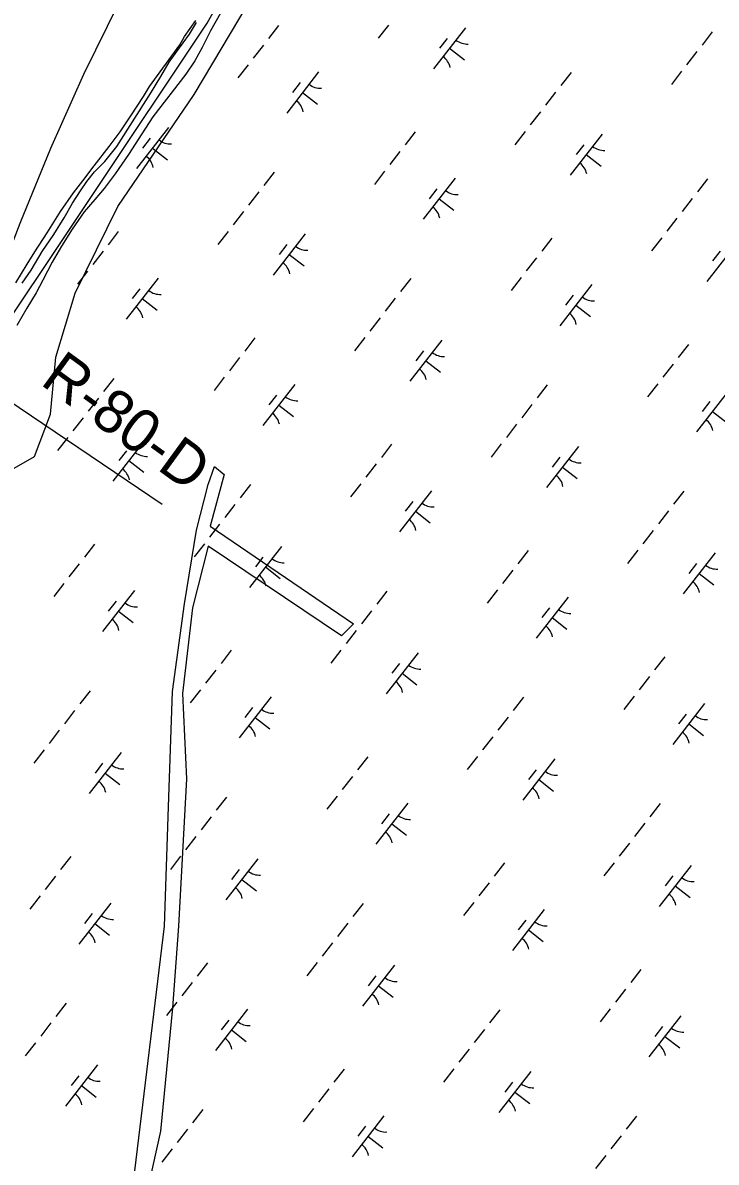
# Model space of a CAD drawing. Extents: x 3888273 to 3909528, y 158682 to 181032.
# Drawn here: x 3898444 to 3899111, y 163473 to 164568 of the extents above; entities that cross this region are included whole.
import ezdxf

# ---------------------------------------------------------------- set-up
doc = ezdxf.new("R2010")
doc.units = 0
for name, color, linetype in [('V-GRID-MAJR', 7, 'Continuous'), ('V-LEVE-TOET', 7, 'Continuous'), ('V-RIVR-EDGE', 7, 'Continuous'), ('V-RIVR-JETY', 7, 'Continuous'), ('V-RIVR-RANG-IDEN', 7, 'Continuous'), ('V-RRAP-FSHR', 7, 'Continuous'), ('V-TOPO-DPTH', 7, 'Continuous'), ('V-TOPO-MINR', 7, 'Continuous'), ('V-WETL-SWMP', 7, 'Continuous')]:
    doc.layers.add(name, color=color, linetype=linetype)

msp = doc.modelspace()

# ---------------------------------------------------------------- linework, layer by layer
at = {"layer": 'V-GRID-MAJR'}
msp.add_spline([(3899339.3, 161091.9), (3899310.2, 162813.4), (3899208, 168873.7), (3899105.7, 174933.9), (3899088.2, 175974.6)], degree=3, dxfattribs=at)
at = {"layer": 'V-LEVE-TOET'}
msp.add_lwpolyline([(3898578.1, 164105.2), (3898383.3, 164236.8), (3898266.7, 164315.1), (3898154.4, 164391.2), (3898098.5, 164425.2)], dxfattribs=at)
at = {"layer": 'V-RIVR-EDGE'}
msp.add_lwpolyline([(3898431.6, 164137.7), (3898455.5, 164151.3), (3898470.9, 164192.2), (3898476, 164246.8), (3898494.7, 164308.2), (3898535.6, 164391.7), (3898609, 164499.1), (3898661.8, 164587.8)], dxfattribs=at)
at = {"layer": 'V-RIVR-JETY'}
for points in [[(3898634.3, 164577.4), (3898624.8, 164560.4), (3898616.6, 164544.4), (3898609.6, 164531.7), (3898601, 164518.9), (3898569.4, 164477.7), (3898558.6, 164461.3), (3898545.9, 164441.7), (3898533.1, 164423.1), (3898522.6, 164409), (3898513.6, 164398.5), (3898503.4, 164386.4), (3898491.9, 164370), (3898481.5, 164353.4), (3898472.6, 164338), (3898463.7, 164321), (3898457, 164308.6), (3898448.1, 164293.9), (3898438.6, 164277.3)], [(3898443.6, 164317.9), (3898452.2, 164330.3), (3898463, 164348.3), (3898474.2, 164364.6), (3898484, 164380.6), (3898492, 164394.7), (3898499.9, 164406.8), (3898506, 164415.6), (3898513.3, 164424.8), (3898523.2, 164434.9), (3898534.7, 164449.4), (3898566.9, 164500.3), (3898577, 164516.4), (3898585, 164530.4), (3898592.3, 164540.6), (3898604.4, 164557.2), (3898611.4, 164568.4)], [(3898551.9, 163465.1), (3898580.6, 163700.2), (3898584.4, 163814.9), (3898588.2, 163925.7), (3898599.7, 164009.8), (3898611.2, 164080.5), (3898622.6, 164124.5), (3898628.4, 164141.7), (3898637.9, 164134.1), (3898624.5, 164084.4), (3898762.2, 163990.7), (3898750.7, 163979.2), (3898622.6, 164065.2), (3898607.3, 164006), (3898597.8, 163923.8), (3898601.6, 163841.6), (3898597.8, 163770.9), (3898594, 163700.2), (3898588.2, 163621.8), (3898576.8, 163503.3), (3898551.9, 163392.5)]]:
    msp.add_lwpolyline(points, dxfattribs=at)
at = {"layer": 'V-RRAP-FSHR'}
msp.add_lwpolyline([(3897334.5, 161278.4), (3897347.1, 161496.1), (3897391.7, 162468.6), (3897415, 162511), (3897527.9, 162698.5), (3897668.8, 162942.7), (3897726.7, 163035.8), (3897814.8, 163180.2), (3897887.5, 163323.2), (3898044.9, 163635.1), (3898398.2, 164233.6), (3898621.6, 164567.9), (3898731.9, 164766.1)], dxfattribs=at)
at = {"layer": 'V-TOPO-DPTH'}
msp.add_lwpolyline([(3897709.5, 163168.8), (3897726, 163254.6), (3897958.8, 163561.8), (3898413.5, 164303), (3898441.8, 164375.6), (3898471.1, 164447.7), (3898502.9, 164518.7), (3898537.2, 164588.3), (3898575.2, 164656), (3898615.6, 164722.5), (3898745.8, 164924.5), (3898762, 164947.9), (3898778.9, 164970.6), (3898797.2, 164992.4), (3898816.4, 165013.4), (3898843.6, 165041.6)], dxfattribs=at)
at = {"layer": 'V-TOPO-MINR'}
msp.add_lwpolyline([(3897709.5, 163168.8), (3897726, 163254.6), (3897958.8, 163561.8), (3898413.5, 164303), (3898441.8, 164375.6), (3898471.1, 164447.7), (3898502.9, 164518.7), (3898537.2, 164588.3), (3898575.2, 164656), (3898615.6, 164722.5), (3898745.8, 164924.5), (3898762, 164947.9), (3898778.9, 164970.6), (3898797.2, 164992.4), (3898816.4, 165013.4), (3898843.6, 165041.6)], dxfattribs=at)
at = {"layer": 'V-WETL-SWMP'}
for p, q in [((3898599.6, 164555), (3898610.5, 164570.4)), ((3898690.2, 164565.6), (3898680.4, 164552.9)), ((3898795.7, 164565.8), (3898785.9, 164553.2)), ((3898869.8, 164563.3), (3898839.1, 164523.9)), ((3898595.1, 164546.8), (3898599.6, 164555)), ((3898852.1, 164553.1), (3898844.7, 164543.6)), ((3899106.9, 164559.3), (3899097.1, 164546.7)), ((3898566, 164506.9), (3898595.1, 164546.8)), ((3898675.5, 164546.6), (3898665.7, 164534)), ((3898854.5, 164543.6), (3898868.7, 164532.6)), ((3899092.2, 164540.4), (3899082.3, 164527.8)), ((3898660.8, 164527.7), (3898650.9, 164515.1)), ((3898728.6, 164520.9), (3898697.9, 164481.4)), ((3898971.2, 164520.5), (3898961.4, 164507.9)), ((3899077.4, 164521.5), (3899067.6, 164508.8)), ((3898560.4, 164497.3), (3898566, 164506.9)), ((3898710.8, 164510.6), (3898703.5, 164501.2)), ((3898548, 164478.7), (3898560.4, 164497.3)), ((3898713.2, 164501.2), (3898727.4, 164490.1)), ((3898956.4, 164501.5), (3898946.6, 164488.9)), ((3898537.8, 164463.2), (3898548, 164478.7)), ((3898941.7, 164482.6), (3898931.9, 164470)), ((3898527.2, 164449.3), (3898537.8, 164463.2)), ((3898584.4, 164467.4), (3898553.7, 164428)), ((3898821.5, 164463.4), (3898811.7, 164450.8)), ((3898927, 164463.7), (3898917.1, 164451)), ((3898566.7, 164457.2), (3898559.3, 164447.7)), ((3899001.1, 164461.2), (3898970.4, 164421.7)), ((3898512.9, 164430.7), (3898527.2, 164449.3)), ((3898569.1, 164447.7), (3898583.3, 164436.6)), ((3898806.8, 164444.5), (3898796.9, 164431.9)), ((3898983.4, 164450.9), (3898976, 164441.5)), ((3898985.8, 164441.5), (3899000, 164430.4)), ((3898501.9, 164416.3), (3898512.9, 164430.7)), ((3898685.8, 164424.6), (3898676, 164411.9)), ((3898792, 164425.5), (3898782.2, 164412.9)), ((3898859.9, 164418.7), (3898829.2, 164379.3)), ((3898492.9, 164404.7), (3898501.9, 164416.3)), ((3898842.1, 164408.5), (3898834.7, 164399)), ((3899102.5, 164418.3), (3899092.6, 164405.7)), ((3898480.4, 164386.9), (3898492.9, 164404.7)), ((3898671.1, 164405.6), (3898661.2, 164393)), ((3898844.5, 164399), (3898858.7, 164388)), ((3899087.7, 164399.4), (3899077.9, 164386.8)), ((3898467.6, 164366.4), (3898480.4, 164386.9)), ((3898656.3, 164386.7), (3898646.5, 164374.1)), ((3899073, 164380.5), (3899063.2, 164367.8)), ((3898455.9, 164348.2), (3898467.6, 164366.4)), ((3898536.1, 164367.5), (3898526.3, 164354.9)), ((3898641.6, 164367.7), (3898631.8, 164355.1)), ((3898715.7, 164365.3), (3898685, 164325.8)), ((3898698, 164355), (3898690.6, 164345.5)), ((3898952.8, 164361.3), (3898943, 164348.7)), ((3899058.3, 164361.5), (3899048.4, 164348.9)), ((3899132.4, 164359), (3899101.7, 164319.6)), ((3898448.4, 164336.2), (3898455.9, 164348.2)), ((3898521.4, 164348.6), (3898511.6, 164335.9)), ((3898700.4, 164345.5), (3898714.6, 164334.5)), ((3898938.1, 164342.3), (3898928.2, 164329.7)), ((3899114.6, 164348.8), (3899107.3, 164339.3)), ((3898437.5, 164318.4), (3898448.4, 164336.2)), ((3898506.6, 164329.6), (3898496.8, 164317)), ((3898574.5, 164322.8), (3898543.8, 164283.4)), ((3898817.1, 164322.4), (3898807.3, 164309.8)), ((3898923.3, 164323.4), (3898913.5, 164310.8)), ((3898556.7, 164312.6), (3898549.4, 164303.1)), ((3898991.2, 164316.6), (3898960.4, 164277.1)), ((3898559.1, 164303.1), (3898573.3, 164292)), ((3898802.3, 164303.5), (3898792.5, 164290.9)), ((3898973.4, 164306.3), (3898966, 164296.9)), ((3898975.8, 164296.9), (3898990, 164285.8)), ((3898787.6, 164284.5), (3898777.8, 164271.9)), ((3898667.4, 164265.4), (3898657.6, 164252.7)), ((3898772.9, 164265.6), (3898763, 164253)), ((3898847, 164263.1), (3898816.3, 164223.7)), ((3899084.1, 164259.1), (3899074.2, 164246.5)), ((3898652.7, 164246.4), (3898642.8, 164233.8)), ((3898829.3, 164252.9), (3898821.9, 164243.4)), ((3898831.7, 164243.4), (3898845.9, 164232.3)), ((3899069.3, 164240.2), (3899059.5, 164227.6)), ((3898531.7, 164226.5), (3898521.9, 164213.9)), ((3898637.9, 164227.5), (3898628.1, 164214.8)), ((3898705.8, 164220.7), (3898675.1, 164181.2)), ((3898688, 164210.4), (3898680.6, 164201)), ((3898948.4, 164220.3), (3898938.5, 164207.7)), ((3899054.6, 164221.3), (3899044.8, 164208.6)), ((3899122.4, 164214.5), (3899091.7, 164175)), ((3898517, 164207.6), (3898507.1, 164194.9)), ((3898690.4, 164200.9), (3898704.6, 164189.9)), ((3898933.6, 164201.3), (3898923.8, 164188.7)), ((3899104.7, 164204.2), (3899097.3, 164194.7)), ((3898502.2, 164188.6), (3898492.4, 164176)), ((3899107.1, 164194.7), (3899121.3, 164183.7)), ((3898918.9, 164182.4), (3898909.1, 164169.8)), ((3898487.5, 164169.7), (3898477.7, 164157.1)), ((3898561.6, 164167.2), (3898530.9, 164127.7)), ((3898543.9, 164157), (3898536.5, 164147.5)), ((3898798.7, 164163.2), (3898788.9, 164150.6)), ((3898904.1, 164163.5), (3898894.3, 164150.8)), ((3898978.3, 164161), (3898947.6, 164121.5)), ((3898546.3, 164147.5), (3898560.5, 164136.4)), ((3898960.5, 164150.7), (3898953.2, 164141.3)), ((3898783.9, 164144.3), (3898774.1, 164131.6)), ((3898962.9, 164141.3), (3898977.1, 164130.2)), ((3898663, 164124.4), (3898653.1, 164111.7)), ((3898769.2, 164125.3), (3898759.4, 164112.7)), ((3898837, 164118.5), (3898806.3, 164079.1)), ((3899079.6, 164118.1), (3899069.8, 164105.5)), ((3898648.2, 164105.4), (3898638.4, 164092.8)), ((3898819.3, 164108.3), (3898811.9, 164098.8)), ((3898821.7, 164098.8), (3898835.9, 164087.8)), ((3899064.9, 164099.2), (3899055.1, 164086.6)), ((3898633.5, 164086.5), (3898623.7, 164073.9)), ((3899050.2, 164080.3), (3899040.3, 164067.6)), ((3898513.3, 164067.3), (3898503.5, 164054.7)), ((3898618.8, 164067.5), (3898608.9, 164054.9)), ((3898692.9, 164065.1), (3898662.2, 164025.6)), ((3898930, 164061.1), (3898920.1, 164048.4)), ((3899035.4, 164061.3), (3899025.6, 164048.7)), ((3899109.6, 164058.8), (3899078.9, 164019.4)), ((3898498.6, 164048.4), (3898488.7, 164035.7)), ((3898675.1, 164054.8), (3898667.8, 164045.3)), ((3899091.8, 164048.6), (3899084.4, 164039.1)), ((3898677.6, 164045.3), (3898691.8, 164034.3)), ((3898915.2, 164042.1), (3898905.4, 164029.5)), ((3899094.2, 164039.1), (3899108.4, 164028.1)), ((3898483.8, 164029.4), (3898474, 164016.8)), ((3898551.7, 164022.6), (3898521, 163983.2)), ((3898794.3, 164022.2), (3898784.4, 164009.6)), ((3898900.5, 164023.2), (3898890.7, 164010.6)), ((3898968.3, 164016.4), (3898937.6, 163976.9)), ((3898533.9, 164012.4), (3898526.5, 164002.9)), ((3898536.3, 164002.9), (3898550.5, 163991.8)), ((3898779.5, 164003.3), (3898769.7, 163990.6)), ((3898950.6, 164006.1), (3898943.2, 163996.7)), ((3898953, 163996.7), (3898967.2, 163985.6)), ((3898764.8, 163984.3), (3898755, 163971.7)), ((3898644.6, 163965.2), (3898634.8, 163952.5)), ((3898750, 163965.4), (3898740.2, 163952.8)), ((3898824.2, 163962.9), (3898793.5, 163923.5)), ((3899061.2, 163958.9), (3899051.4, 163946.3)), ((3898806.4, 163952.7), (3898799.1, 163943.2)), ((3898629.8, 163946.2), (3898620, 163933.6)), ((3898808.8, 163943.2), (3898823, 163932.1)), ((3899046.5, 163940), (3899036.7, 163927.4)), ((3898508.9, 163926.3), (3898499, 163913.7)), ((3898615.1, 163927.3), (3898605.3, 163914.6)), ((3898682.9, 163920.5), (3898652.2, 163881)), ((3898925.5, 163920.1), (3898915.7, 163907.4)), ((3899031.8, 163921), (3899021.9, 163908.4)), ((3898494.1, 163907.4), (3898484.3, 163894.7)), ((3898665.2, 163910.2), (3898657.8, 163900.7)), ((3899099.6, 163914.2), (3899068.9, 163874.8)), ((3899081.9, 163904), (3899074.5, 163894.5)), ((3898667.6, 163900.7), (3898681.8, 163889.7)), ((3898910.8, 163901.1), (3898901, 163888.5)), ((3899084.3, 163894.5), (3899098.5, 163883.5)), ((3898479.4, 163888.4), (3898469.6, 163875.8)), ((3898896.1, 163882.2), (3898886.2, 163869.6)), ((3898464.7, 163869.5), (3898454.8, 163856.8)), ((3898538.8, 163867), (3898508.1, 163827.5)), ((3898775.9, 163863), (3898766, 163850.4)), ((3898881.3, 163863.2), (3898871.5, 163850.6)), ((3898955.5, 163860.8), (3898924.8, 163821.3)), ((3898521, 163856.7), (3898513.7, 163847.3)), ((3898937.7, 163850.5), (3898930.3, 163841)), ((3898523.4, 163847.3), (3898537.7, 163836.2)), ((3898761.1, 163844.1), (3898751.3, 163831.4)), ((3898940.1, 163841), (3898954.3, 163830)), ((3898640.1, 163824.2), (3898630.3, 163811.5)), ((3898746.4, 163825.1), (3898736.6, 163812.5)), ((3898814.2, 163818.3), (3898783.5, 163778.9)), ((3899056.8, 163817.9), (3899047, 163805.3)), ((3898796.5, 163808.1), (3898789.1, 163798.6)), ((3898625.4, 163805.2), (3898615.6, 163792.6)), ((3898798.9, 163798.6), (3898813.1, 163787.5)), ((3899042.1, 163799), (3899032.3, 163786.4)), ((3898610.7, 163786.3), (3898600.8, 163773.6)), ((3899027.3, 163780), (3899017.5, 163767.4)), ((3898490.5, 163767.1), (3898480.6, 163754.5)), ((3898595.9, 163767.3), (3898586.1, 163754.7)), ((3898670.1, 163764.9), (3898639.4, 163725.4)), ((3898652.3, 163754.6), (3898645, 163745.1)), ((3898907.1, 163760.9), (3898897.3, 163748.2)), ((3899012.6, 163761.1), (3899002.8, 163748.5)), ((3899086.7, 163758.6), (3899056, 163719.2)), ((3898475.7, 163748.1), (3898465.9, 163735.5)), ((3898654.7, 163745.1), (3898668.9, 163734.1)), ((3898892.4, 163741.9), (3898882.6, 163729.3)), ((3899069, 163748.4), (3899061.6, 163738.9)), ((3898461, 163729.2), (3898451.2, 163716.6)), ((3899071.4, 163738.9), (3899085.6, 163727.8)), ((3898528.8, 163722.4), (3898498.1, 163682.9)), ((3898771.4, 163722), (3898761.6, 163709.4)), ((3898877.7, 163723), (3898867.8, 163710.4)), ((3898511.1, 163712.2), (3898503.7, 163702.7)), ((3898945.5, 163716.2), (3898914.8, 163676.7)), ((3898513.5, 163702.7), (3898527.7, 163691.6)), ((3898756.7, 163703.1), (3898746.9, 163690.4)), ((3898927.7, 163705.9), (3898920.4, 163696.5)), ((3898930.2, 163696.5), (3898944.4, 163685.4)), ((3898742, 163684.1), (3898732.1, 163671.5)), ((3898621.8, 163664.9), (3898611.9, 163652.3)), ((3898727.2, 163665.2), (3898717.4, 163652.6)), ((3898801.4, 163662.7), (3898770.7, 163623.3)), ((3898783.6, 163652.5), (3898776.2, 163643)), ((3899038.4, 163658.7), (3899028.6, 163646.1)), ((3898607, 163646), (3898597.2, 163633.4)), ((3898786, 163643), (3898800.2, 163631.9)), ((3899023.7, 163639.8), (3899013.9, 163627.1)), ((3898486, 163626.1), (3898476.2, 163613.5)), ((3898592.3, 163627.1), (3898582.5, 163614.4)), ((3898660.1, 163620.3), (3898629.4, 163580.8)), ((3898902.7, 163619.9), (3898892.9, 163607.2)), ((3899008.9, 163620.8), (3898999.1, 163608.2)), ((3898642.4, 163610), (3898635, 163600.5)), ((3899076.8, 163614), (3899046.1, 163574.6)), ((3898471.3, 163607.2), (3898461.5, 163594.5)), ((3898644.8, 163600.5), (3898659, 163589.5)), ((3898888, 163600.9), (3898878.1, 163588.3)), ((3899059, 163603.8), (3899051.7, 163594.3)), ((3898456.6, 163588.2), (3898446.7, 163575.6)), ((3899061.4, 163594.3), (3899075.6, 163583.3)), ((3898873.2, 163582), (3898863.4, 163569.4)), ((3898516, 163566.8), (3898485.3, 163527.3)), ((3898498.2, 163556.5), (3898490.8, 163547.1)), ((3898753, 163562.8), (3898743.2, 163550.2)), ((3898858.5, 163563), (3898848.7, 163550.4)), ((3898932.6, 163560.6), (3898901.9, 163521.1)), ((3898500.6, 163547.1), (3898514.8, 163536)), ((3898738.3, 163543.9), (3898728.5, 163531.2)), ((3898914.9, 163550.3), (3898907.5, 163540.8)), ((3898917.3, 163540.8), (3898931.5, 163529.8)), ((3898617.3, 163523.9), (3898607.5, 163511.3)), ((3898723.6, 163524.9), (3898713.7, 163512.3)), ((3898791.4, 163518.1), (3898760.7, 163478.7)), ((3899034, 163517.7), (3899024.2, 163505.1)), ((3898602.6, 163505), (3898592.8, 163492.4)), ((3898773.6, 163507.9), (3898766.3, 163498.4)), ((3898776, 163498.4), (3898790.3, 163487.3)), ((3899019.3, 163498.8), (3899009.4, 163486.2)), ((3898587.8, 163486.1), (3898578, 163473.4)), ((3899004.5, 163479.8), (3898994.7, 163467.2))]:
    msp.add_line(p, q, dxfattribs=at)
for centre, start, end in [((3898871.6, 164565.3), 231.343, 272.8866), ((3898837.7, 164521.7), 11.343, 52.8866), ((3898730.4, 164522.8), 231.343, 272.8866), ((3898696.5, 164479.2), 11.343, 52.8866), ((3898586.2, 164469.3), 231.343, 272.8866), ((3899002.9, 164463.1), 231.343, 272.8866), ((3898552.3, 164425.7), 11.343, 52.8866), ((3898969, 164419.5), 11.343, 52.8866), ((3898861.7, 164420.7), 231.343, 272.8866), ((3898827.7, 164377.1), 11.343, 52.8866), ((3898717.5, 164367.2), 231.343, 272.8866), ((3898683.6, 164323.6), 11.343, 52.8866), ((3898576.3, 164324.7), 231.343, 272.8866), ((3898993, 164318.5), 231.343, 272.8866), ((3898542.4, 164281.1), 11.343, 52.8866), ((3898959, 164274.9), 11.343, 52.8866), ((3898848.8, 164265.1), 231.343, 272.8866), ((3898814.9, 164221.5), 11.343, 52.8866), ((3898707.6, 164222.6), 231.343, 272.8866), ((3898673.6, 164179), 11.343, 52.8866), ((3899090.3, 164172.8), 11.343, 52.8866), ((3898563.4, 164169.1), 231.343, 272.8866), ((3898980.1, 164162.9), 231.343, 272.8866), ((3898529.5, 164125.5), 11.343, 52.8866), ((3898946.2, 164119.3), 11.343, 52.8866), ((3898838.8, 164120.5), 231.343, 272.8866), ((3898804.9, 164076.9), 11.343, 52.8866), ((3898694.7, 164067), 231.343, 272.8866), ((3899111.4, 164060.8), 231.343, 272.8866), ((3898660.8, 164023.4), 11.343, 52.8866), ((3899077.4, 164017.2), 11.343, 52.8866), ((3898553.5, 164024.5), 231.343, 272.8866), ((3898970.1, 164018.3), 231.343, 272.8866), ((3898519.5, 163980.9), 11.343, 52.8866), ((3898936.2, 163974.7), 11.343, 52.8866), ((3898826, 163964.8), 231.343, 272.8866), ((3898792.1, 163921.2), 11.343, 52.8866), ((3898684.7, 163922.4), 231.343, 272.8866), ((3899101.4, 163916.2), 231.343, 272.8866), ((3898650.8, 163878.8), 11.343, 52.8866), ((3899067.5, 163872.6), 11.343, 52.8866), ((3898540.6, 163868.9), 231.343, 272.8866), ((3898506.7, 163825.3), 11.343, 52.8866), ((3898957.3, 163862.7), 231.343, 272.8866), ((3898923.3, 163819.1), 11.343, 52.8866), ((3898816, 163820.3), 231.343, 272.8866), ((3898782.1, 163776.7), 11.343, 52.8866), ((3898671.9, 163766.8), 231.343, 272.8866), ((3899088.5, 163760.6), 231.343, 272.8866), ((3898638, 163723.2), 11.343, 52.8866), ((3899054.6, 163717), 11.343, 52.8866), ((3898530.6, 163724.3), 231.343, 272.8866), ((3898947.3, 163718.1), 231.343, 272.8866), ((3898496.7, 163680.7), 11.343, 52.8866), ((3898913.4, 163674.5), 11.343, 52.8866), ((3898803.2, 163664.6), 231.343, 272.8866), ((3898769.2, 163621), 11.343, 52.8866), ((3898661.9, 163622.2), 231.343, 272.8866), ((3899078.6, 163616), 231.343, 272.8866), ((3898628, 163578.6), 11.343, 52.8866), ((3899044.7, 163572.4), 11.343, 52.8866), ((3898517.8, 163568.7), 231.343, 272.8866), ((3898934.4, 163562.5), 231.343, 272.8866), ((3898483.8, 163525.1), 11.343, 52.8866), ((3898900.5, 163518.9), 11.343, 52.8866), ((3898793.2, 163520), 231.343, 272.8866), ((3898759.3, 163476.4), 11.343, 52.8866)]:
    msp.add_arc(centre, 17.6, start, end, dxfattribs=at)

# ---------------------------------------------------------------- texts
at = {"layer": 'V-RIVR-RANG-IDEN'}
msp.add_text('R-80-D', height=41.5, rotation=323.946, dxfattribs=at).set_placement((3898460, 164221.4))

doc.saveas('drawing.dxf')
